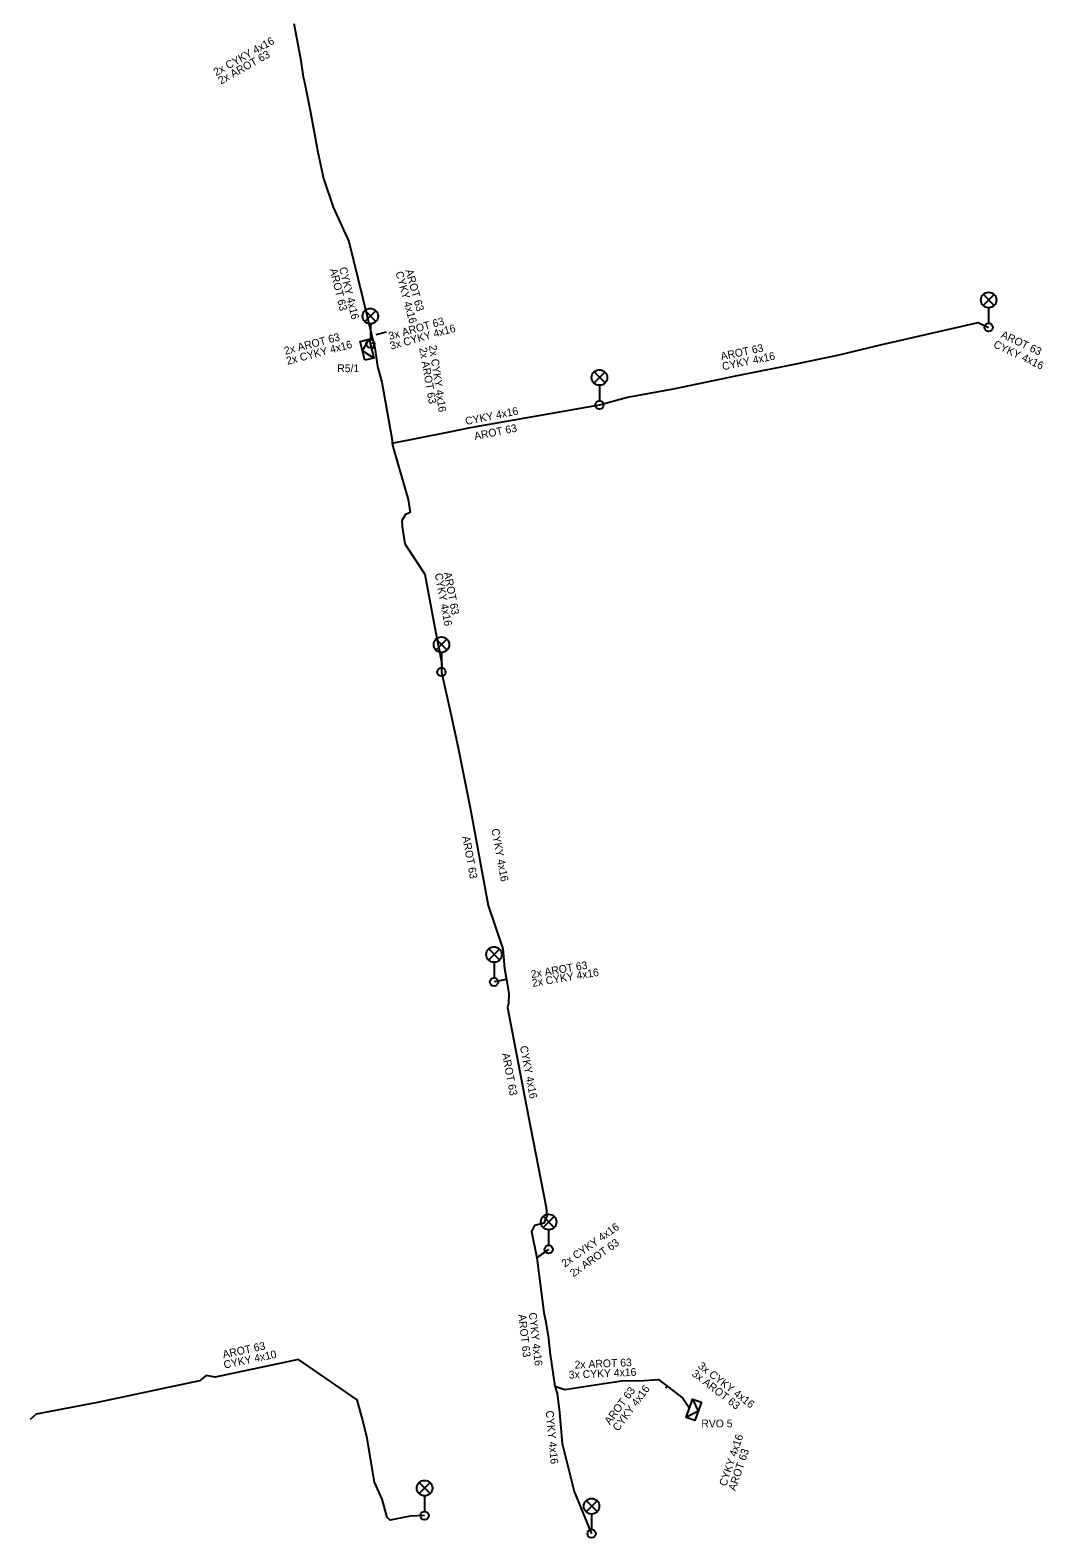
# Model space of a CAD drawing. Extents: x -641884 to -641258, y -1196509 to -1195931.
# Drawn here: x -641791.2 to -641693.4, y -1196508.8 to -1196363.4 of the extents above; entities that cross this region are included whole.
import ezdxf

# ---------------------------------------------------------------- set-up
doc = ezdxf.new("R2010")
doc.units = 0
for name, color, linetype in [('CIZÍ_NADZEM', 7, 'Continuous'), ('CIZÍ_NADZEM_POPIS', 7, 'Continuous'), ('TECH_OCHR_PÁSMO_HRAN', 7, 'Continuous'), ('Vrstva 22', 7, 'Continuous'), ('Vrstva 31', 7, 'Continuous'), ('ZP_EON', 7, 'Continuous'), ('ZP_EON_POPIS', 7, 'Continuous')]:
    doc.layers.add(name, color=color, linetype=linetype)

msp = doc.modelspace()

# ---------------------------------------------------------------- linework, layer by layer
at = {"layer": 'CIZÍ_NADZEM'}
for points in [[(-641758.89, -1196395.22), (-641759.34, -1196393.4), (-641758.47, -1196393.18), (-641758.01, -1196395)], [(-641726.42, -1196495.76), (-641727.05, -1196497.53), (-641727.89, -1196497.22), (-641727.27, -1196495.46)]]:
    msp.add_lwpolyline(points, close=True, dxfattribs=at)
for points in [[(-641758.01, -1196395), (-641759.11, -1196394.31), (-641758.47, -1196393.18)], [(-641727.27, -1196495.46), (-641726.73, -1196496.64), (-641727.89, -1196497.22)]]:
    msp.add_lwpolyline(points, dxfattribs=at)
at = {"layer": 'TECH_OCHR_PÁSMO_HRAN'}
for p, q in [((-641756.83, -1196392.49), (-641757.82, -1196392.75)), ((-641757.95, -1196394.01), (-641758.25, -1196394.1)), ((-641758.07, -1196393.53), (-641757.94, -1196394)), ((-641745.22, -1196454.97), (-641746.43, -1196455.21)), ((-641742.29, -1196481.82), (-641741.16, -1196481.02)), ((-641729.74, -1196494.2), (-641729.86, -1196494.36)), ((-641727.58, -1196496.34), (-641727.36, -1196495.69))]:
    msp.add_line(p, q, dxfattribs=at)
for points in [[(-641765.75, -1196362.71), (-641765.11, -1196366.08), (-641764.84, -1196367.88), (-641764.71, -1196368.37), (-641764.18, -1196371.1), (-641763.43, -1196375.14), (-641762.88, -1196377.68), (-641761.95, -1196380.43), (-641760.43, -1196383.74), (-641759.08, -1196389.25), (-641758.07, -1196393.53)], [(-641736.26, -1196399.53), (-641733.54, -1196398.79), (-641729.13, -1196397.98), (-641722.94, -1196396.69), (-641717.28, -1196395.56), (-641713.13, -1196394.68), (-641709.14, -1196393.74), (-641699.73, -1196391.57), (-641698.71, -1196392.05)], [(-641757.94, -1196394), (-641757.67, -1196395.82), (-641757.24, -1196397.32), (-641756.25, -1196402.94), (-641756.24, -1196403.23)], [(-641756.24, -1196403.23), (-641750.88, -1196402.14), (-641748.71, -1196401.7), (-641736.26, -1196399.53)], [(-641756.24, -1196403.23), (-641756.13, -1196403.77), (-641754.72, -1196408.64), (-641754.52, -1196409.91), (-641754.96, -1196410.11), (-641755.31, -1196410.68), (-641755.29, -1196411.25), (-641755.03, -1196412.92), (-641753.12, -1196415.87), (-641752.15, -1196421.05), (-641751.45, -1196424.49), (-641751.5, -1196425.31)], [(-641751.5, -1196425.31), (-641750.56, -1196429.48), (-641749.88, -1196432.62), (-641748.69, -1196438.55), (-641746.98, -1196447.82), (-641745.59, -1196452.02), (-641745.41, -1196453.92), (-641745.22, -1196454.97)], [(-641745.22, -1196454.97), (-641745.01, -1196456.33), (-641745.02, -1196457.28), (-641745.13, -1196457.67), (-641743.17, -1196467.9), (-641741.41, -1196476.96), (-641741.32, -1196477.82), (-641741.61, -1196478.47), (-641742.54, -1196478.7), (-641742.82, -1196479.29), (-641742.29, -1196481.82)], [(-641742.29, -1196481.82), (-641741.93, -1196484.59), (-641741.64, -1196487.09), (-641741.44, -1196488.05), (-641741.19, -1196489.61), (-641741.04, -1196490.94), (-641740.55, -1196494.2)], [(-641753.13, -1196506.7), (-641754.52, -1196506.76), (-641756.46, -1196507.15), (-641756.74, -1196506.87), (-641757.22, -1196505.11), (-641757.97, -1196503.46), (-641758.7, -1196499.07), (-641759.18, -1196497.17), (-641759.64, -1196495.53), (-641765.28, -1196491.65), (-641773.33, -1196493.35), (-641774.19, -1196493.17), (-641774.84, -1196493.7), (-641774.84, -1196493.7), (-641784.68, -1196495.8), (-641790.61, -1196496.92), (-641791.18, -1196497.42)], [(-641740.55, -1196494.2), (-641739.6, -1196494.52), (-641735.85, -1196493.96), (-641734.09, -1196493.7), (-641731.99, -1196493.65), (-641730.56, -1196493.56), (-641729.74, -1196494.2)], [(-641740.55, -1196494.2), (-641740.34, -1196494.93), (-641740.12, -1196496.74), (-641739.84, -1196499.73), (-641738.7, -1196504.37), (-641737.02, -1196508.45)], [(-641729.74, -1196494.2), (-641728.23, -1196495.37), (-641727.58, -1196496.34)]]:
    msp.add_lwpolyline(points, dxfattribs=at)
at = {"layer": 'Vrstva 31'}
for p, q in [((-641699.24, -1196389.93), (-641698.18, -1196388.87)), ((-641698.17, -1196389.92), (-641699.22, -1196388.86)), ((-641758.89, -1196391.49), (-641757.83, -1196390.43)), ((-641757.82, -1196391.48), (-641758.87, -1196390.42)), ((-641698.71, -1196390.15), (-641698.71, -1196391.65)), ((-641758.36, -1196391.71), (-641758.36, -1196393.21)), ((-641736.79, -1196397.41), (-641735.73, -1196396.35)), ((-641735.72, -1196397.4), (-641736.77, -1196396.34)), ((-641736.26, -1196397.63), (-641736.26, -1196399.13)), ((-641752.03, -1196423.19), (-641750.97, -1196422.13)), ((-641750.96, -1196423.18), (-641752.01, -1196422.12)), ((-641751.5, -1196423.41), (-641751.5, -1196424.91)), ((-641746.96, -1196453.09), (-641745.9, -1196452.03)), ((-641745.89, -1196453.08), (-641746.94, -1196452.02)), ((-641746.43, -1196453.31), (-641746.43, -1196454.81)), ((-641741.69, -1196478.9), (-641740.63, -1196477.84)), ((-641740.62, -1196478.89), (-641741.67, -1196477.83)), ((-641741.16, -1196479.12), (-641741.16, -1196480.62)), ((-641753.66, -1196504.58), (-641752.6, -1196503.52)), ((-641752.59, -1196504.57), (-641753.64, -1196503.51)), ((-641753.13, -1196504.8), (-641753.13, -1196506.3)), ((-641737.55, -1196506.33), (-641736.49, -1196505.27)), ((-641736.48, -1196506.32), (-641737.53, -1196505.26)), ((-641737.02, -1196506.55), (-641737.02, -1196508.05))]:
    msp.add_line(p, q, dxfattribs=at)
for centre, radius in [((-641698.71, -1196389.4), 0.75), ((-641758.36, -1196390.96), 0.75), ((-641698.71, -1196392.05), 0.4), ((-641758.36, -1196393.61), 0.4), ((-641736.26, -1196396.88), 0.75), ((-641736.26, -1196399.53), 0.4), ((-641751.5, -1196422.66), 0.75), ((-641751.5, -1196425.31), 0.4), ((-641746.43, -1196452.56), 0.75), ((-641746.43, -1196455.21), 0.4), ((-641741.16, -1196478.37), 0.75), ((-641741.16, -1196481.02), 0.4), ((-641753.13, -1196504.05), 0.75), ((-641737.02, -1196505.8), 0.75), ((-641753.13, -1196506.7), 0.4), ((-641737.02, -1196508.45), 0.4)]:
    msp.add_circle(centre, radius, dxfattribs=at)
at = {"layer": 'ZP_EON'}
for p, q in [((-641758.07, -1196393.53), (-641758.36, -1196393.61)), ((-641757.94, -1196394), (-641758.24, -1196394.09)), ((-641758.07, -1196393.53), (-641757.94, -1196394)), ((-641745.22, -1196454.97), (-641746.43, -1196455.21)), ((-641741.16, -1196481.02), (-641742.29, -1196481.82)), ((-641729.86, -1196494.36), (-641729.74, -1196494.2)), ((-641727.58, -1196496.34), (-641727.36, -1196495.69))]:
    msp.add_line(p, q, dxfattribs=at)
for points in [[(-641765.75, -1196362.71), (-641765.11, -1196366.08), (-641764.84, -1196367.88), (-641764.71, -1196368.37), (-641764.18, -1196371.1), (-641763.43, -1196375.14), (-641762.88, -1196377.68), (-641761.95, -1196380.43), (-641760.43, -1196383.74), (-641759.08, -1196389.25), (-641758.07, -1196393.53)], [(-641736.26, -1196399.53), (-641733.54, -1196398.79), (-641729.13, -1196397.98), (-641722.94, -1196396.69), (-641717.28, -1196395.56), (-641713.13, -1196394.68), (-641709.14, -1196393.74), (-641699.73, -1196391.57), (-641698.71, -1196392.05)], [(-641757.94, -1196394), (-641757.67, -1196395.82), (-641757.24, -1196397.32), (-641756.25, -1196402.94), (-641756.24, -1196403.23)], [(-641756.24, -1196403.23), (-641750.88, -1196402.14), (-641748.71, -1196401.7), (-641736.26, -1196399.53)], [(-641756.24, -1196403.23), (-641756.13, -1196403.77), (-641754.72, -1196408.64), (-641754.52, -1196409.91), (-641754.96, -1196410.11), (-641755.31, -1196410.68), (-641755.29, -1196411.25), (-641755.03, -1196412.92), (-641753.12, -1196415.87), (-641752.15, -1196421.05), (-641751.45, -1196424.49), (-641751.5, -1196425.31)], [(-641751.5, -1196425.31), (-641750.56, -1196429.48), (-641749.88, -1196432.62), (-641748.69, -1196438.55), (-641746.98, -1196447.82), (-641745.59, -1196452.02), (-641745.41, -1196453.92), (-641745.22, -1196454.97)], [(-641745.22, -1196454.97), (-641745.01, -1196456.33), (-641745.02, -1196457.28), (-641745.13, -1196457.67), (-641743.17, -1196467.9), (-641741.41, -1196476.96), (-641741.32, -1196477.82), (-641741.61, -1196478.47), (-641742.54, -1196478.7), (-641742.82, -1196479.29), (-641742.29, -1196481.82)], [(-641742.29, -1196481.82), (-641741.93, -1196484.59), (-641741.64, -1196487.09), (-641741.44, -1196488.05), (-641741.19, -1196489.61), (-641741.04, -1196490.94), (-641740.55, -1196494.2)], [(-641753.13, -1196506.7), (-641754.52, -1196506.76), (-641756.46, -1196507.15), (-641756.74, -1196506.87), (-641757.22, -1196505.11), (-641757.97, -1196503.46), (-641758.7, -1196499.07), (-641759.18, -1196497.17), (-641759.64, -1196495.53), (-641765.28, -1196491.65), (-641773.33, -1196493.35), (-641774.19, -1196493.17), (-641774.84, -1196493.7), (-641774.84, -1196493.7), (-641784.68, -1196495.8), (-641790.61, -1196496.92), (-641791.18, -1196497.42)], [(-641740.55, -1196494.2), (-641739.6, -1196494.52), (-641735.85, -1196493.96), (-641734.09, -1196493.7), (-641731.99, -1196493.65), (-641730.56, -1196493.56), (-641729.74, -1196494.2)], [(-641740.55, -1196494.2), (-641740.34, -1196494.93), (-641740.12, -1196496.74), (-641739.84, -1196499.73), (-641738.7, -1196504.37), (-641737.02, -1196508.45)], [(-641729.74, -1196494.2), (-641728.23, -1196495.37), (-641727.58, -1196496.34)]]:
    msp.add_lwpolyline(points, dxfattribs=at)

# ---------------------------------------------------------------- texts
at = {"layer": 'CIZÍ_NADZEM_POPIS'}
for s, p in [('R5/1', (-641761.55, -1196396.36)), ('RVO 5', (-641726.43, -1196498.19))]:
    msp.add_text(s, height=0.75, dxfattribs=at).set_placement(p)
at = {"layer": 'Vrstva 22'}
for s, rotation, p in [('2x AROT 63', 29.2753, (-641772.78, -1196368.62)), ('AROT 63', 283.7668, (-641762.29, -1196386.45)), ('AROT 63', 285.4612, (-641754.99, -1196386.54)), ('3x AROT 63', 15.7672, (-641756.48, -1196393.26)), ('2x AROT 63', 14.7151, (-641766.57, -1196394.69)), ('AROT 63', 334.7989, (-641697.6, -1196393)), ('2x AROT 63', 279.9905, (-641753.66, -1196394.04)), ('AROT 63', 11.772, (-641724.48, -1196395.21)), ('AROT 63', 11.4622, (-641748.26, -1196402.92)), ('AROT 63', 280.6063, (-641751.27, -1196415.72)), ('AROT 63', 280.4516, (-641749.5, -1196441.19)), ('2x AROT 63', 9.5366, (-641742.81, -1196454.84)), ('AROT 63', 280.8461, (-641745.67, -1196462.13)), ('2x AROT 63', 35.2971, (-641738.78, -1196483.72)), ('AROT 63', 276.6167, (-641744.1, -1196487.31)), ('AROT 63', 11.9245, (-641772.53, -1196491.52)), ('2x AROT 63', 2.5001, (-641738.64, -1196492.52)), ('3x AROT 63', 322.2302, (-641727.42, -1196493.14)), ('AROT 63', 53.1301, (-641735.26, -1196497.98)), ('AROT 63', 71.301, (-641723.15, -1196504.36))]:
    msp.add_text(s, height=0.75, rotation=rotation, dxfattribs=at).set_placement(p)
at = {"layer": 'ZP_EON_POPIS'}
for s, rotation, p in [('2x CYKY 4x16', 29.2753, (-641773.24, -1196367.81)), ('CYKY 4x16', 283.7668, (-641761.38, -1196386.31)), ('CYKY 4x16', 285.4612, (-641755.95, -1196386.74)), ('3x CYKY 4x16', 15.7672, (-641756.35, -1196394.21)), ('2x CYKY 4x16', 14.7151, (-641766.36, -1196395.66)), ('CYKY 4x16', 334.7989, (-641698.31, -1196393.93)), ('2x CYKY 4x16', 278.4384, (-641752.71, -1196393.81)), ('CYKY 4x16', 11.772, (-641724.34, -1196396.19)), ('CYKY 4x16', 11.4622, (-641749.12, -1196401.47)), ('CYKY 4x16', 280.6063, (-641752.15, -1196415.82)), ('CYKY 4x16', 280.4516, (-641746.69, -1196440.47)), ('2x CYKY 4x16', 9.5366, (-641742.7, -1196455.69)), ('CYKY 4x16', 280.8461, (-641743.94, -1196461.43)), ('2x CYKY 4x16', 35.2971, (-641739.6, -1196482.78)), ('CYKY 4x16', 276.6167, (-641743.08, -1196487.14)), ('CYKY 4x10', 11.9245, (-641772.43, -1196492.53)), ('3x CYKY 4x16', 322.1591, (-641726.82, -1196492.39)), ('3x CYKY 4x16', 2.5001, (-641739.2, -1196493.49)), ('CYKY 4x16', 53.1301, (-641734.46, -1196498.62)), ('CYKY 4x16', 275.3499, (-641741.44, -1196496.6)), ('CYKY 4x16', 71.301, (-641724.03, -1196503.92))]:
    msp.add_text(s, height=0.75, rotation=rotation, dxfattribs=at).set_placement(p)

doc.saveas('drawing.dxf')
